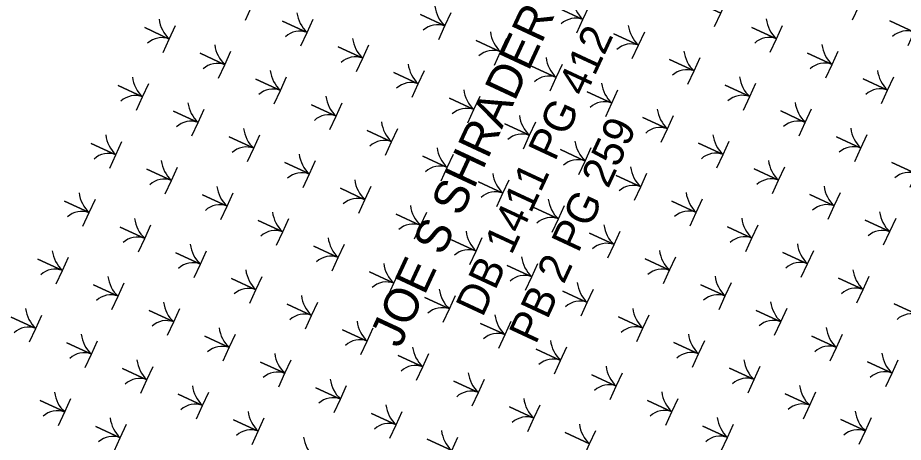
# Model space of a CAD drawing. Extents: x 2532037 to 2533565, y 713396 to 716867.
# Drawn here: x 2532692.9 to 2532822.3, y 715755.3 to 715817.2 of the extents above; entities that cross this region are included whole.
import ezdxf

# ---------------------------------------------------------------- set-up
doc = ezdxf.new("R2010")
doc.units = 0
for name, color, linetype in [('Exist Property Deed Book Text', 7, 'Continuous'), ('Exist Property Owner Text', 7, 'Continuous'), ('Scratch_Level_1', 7, 'Continuous')]:
    doc.layers.add(name, color=color, linetype=linetype)

msp = doc.modelspace()

# ---------------------------------------------------------------- linework, layer by layer
at = {"layer": 'Scratch_Level_1'}
for points in [[(2532726.17, 715816.87), (2532727.07, 715818.82), (2532723.49, 715820.47), (2532727.07, 715818.82), (2532727.97, 715820.77)], [(2532794.71, 715815.95), (2532795.62, 715817.91), (2532792.03, 715819.56), (2532795.62, 715817.91), (2532796.52, 715819.86)], [(2532814.86, 715816.9), (2532815.76, 715818.85), (2532812.17, 715820.51), (2532815.76, 715818.85), (2532816.66, 715820.8)], [(2532774.57, 715815.01), (2532775.47, 715816.96), (2532771.89, 715818.61), (2532775.47, 715816.96), (2532776.38, 715818.91)], [(2532754.43, 715814.06), (2532755.33, 715816.02), (2532751.75, 715817.67), (2532755.33, 715816.02), (2532756.23, 715817.97)], [(2532714.15, 715812.17), (2532715.05, 715814.12), (2532711.47, 715815.78), (2532715.05, 715814.12), (2532715.95, 715816.08)], [(2532734.29, 715813.12), (2532735.19, 715815.07), (2532731.61, 715816.72), (2532735.19, 715815.07), (2532736.09, 715817.02)], [(2532802.84, 715812.2), (2532803.74, 715814.16), (2532800.15, 715815.81), (2532803.74, 715814.16), (2532804.64, 715816.11)], [(2532822.98, 715813.15), (2532823.88, 715815.1), (2532820.3, 715816.76), (2532823.88, 715815.1), (2532824.78, 715817.05)], [(2532782.69, 715811.26), (2532783.6, 715813.21), (2532780.01, 715814.86), (2532783.6, 715813.21), (2532784.5, 715815.16)], [(2532742.41, 715809.37), (2532743.31, 715811.32), (2532739.73, 715812.97), (2532743.31, 715811.32), (2532744.21, 715813.27)], [(2532762.55, 715810.31), (2532763.45, 715812.27), (2532759.87, 715813.92), (2532763.45, 715812.27), (2532764.36, 715814.22)], [(2532722.27, 715808.42), (2532723.17, 715810.37), (2532719.59, 715812.03), (2532723.17, 715810.37), (2532724.07, 715812.33)], [(2532810.96, 715808.46), (2532811.86, 715810.41), (2532808.28, 715812.06), (2532811.86, 715810.41), (2532812.76, 715812.36)], [(2532790.82, 715807.51), (2532791.72, 715809.46), (2532788.13, 715811.12), (2532791.72, 715809.46), (2532792.62, 715811.41)], [(2532750.53, 715805.62), (2532751.43, 715807.57), (2532747.85, 715809.22), (2532751.43, 715807.57), (2532752.34, 715809.52)], [(2532770.67, 715806.56), (2532771.58, 715808.52), (2532767.99, 715810.17), (2532771.58, 715808.52), (2532772.48, 715810.47)], [(2532730.39, 715804.67), (2532731.29, 715806.63), (2532727.71, 715808.28), (2532731.29, 715806.63), (2532732.19, 715808.58)], [(2532819.08, 715804.71), (2532819.98, 715806.66), (2532816.4, 715808.31), (2532819.98, 715806.66), (2532820.88, 715808.61)], [(2532710.25, 715803.73), (2532711.15, 715805.68), (2532707.57, 715807.33), (2532711.15, 715805.68), (2532712.05, 715807.63)], [(2532798.94, 715803.76), (2532799.84, 715805.71), (2532796.26, 715807.37), (2532799.84, 715805.71), (2532800.74, 715807.66)], [(2532758.65, 715801.87), (2532759.56, 715803.82), (2532755.97, 715805.47), (2532759.56, 715803.82), (2532760.46, 715805.77)], [(2532778.8, 715802.81), (2532779.7, 715804.77), (2532776.11, 715806.42), (2532779.7, 715804.77), (2532780.6, 715806.72)], [(2532738.51, 715800.92), (2532739.41, 715802.88), (2532735.83, 715804.53), (2532739.41, 715802.88), (2532740.32, 715804.83)], [(2532718.37, 715799.98), (2532719.27, 715801.93), (2532715.69, 715803.58), (2532719.27, 715801.93), (2532720.17, 715803.88)], [(2532786.92, 715799.07), (2532787.82, 715801.02), (2532784.24, 715802.67), (2532787.82, 715801.02), (2532788.72, 715802.97)], [(2532807.06, 715800.01), (2532807.96, 715801.96), (2532804.38, 715803.62), (2532807.96, 715801.96), (2532808.86, 715803.92)], [(2532766.78, 715798.12), (2532767.68, 715800.07), (2532764.09, 715801.73), (2532767.68, 715800.07), (2532768.58, 715802.02)], [(2532746.63, 715797.17), (2532747.54, 715799.13), (2532743.95, 715800.78), (2532747.54, 715799.13), (2532748.44, 715801.08)], [(2532706.35, 715795.28), (2532707.25, 715797.24), (2532703.67, 715798.89), (2532707.25, 715797.24), (2532708.15, 715799.19)], [(2532726.49, 715796.23), (2532727.39, 715798.18), (2532723.81, 715799.83), (2532727.39, 715798.18), (2532728.3, 715800.13)], [(2532795.04, 715795.32), (2532795.94, 715797.27), (2532792.36, 715798.92), (2532795.94, 715797.27), (2532796.84, 715799.22)], [(2532815.18, 715796.26), (2532816.08, 715798.21), (2532812.5, 715799.87), (2532816.08, 715798.21), (2532816.98, 715800.17)], [(2532774.9, 715794.37), (2532775.8, 715796.32), (2532772.22, 715797.98), (2532775.8, 715796.32), (2532776.7, 715798.27)], [(2532754.76, 715793.42), (2532755.66, 715795.38), (2532752.08, 715797.03), (2532755.66, 715795.38), (2532756.56, 715797.33)], [(2532823.3, 715792.51), (2532824.2, 715794.46), (2532820.62, 715796.12), (2532824.2, 715794.46), (2532825.1, 715796.42)], [(2532714.47, 715791.53), (2532715.37, 715793.49), (2532711.79, 715795.14), (2532715.37, 715793.49), (2532716.28, 715795.44)], [(2532734.61, 715792.48), (2532735.52, 715794.43), (2532731.93, 715796.08), (2532735.52, 715794.43), (2532736.42, 715796.38)], [(2532803.16, 715791.57), (2532804.06, 715793.52), (2532800.48, 715795.17), (2532804.06, 715793.52), (2532804.96, 715795.47)], [(2532783.02, 715790.62), (2532783.92, 715792.57), (2532780.34, 715794.23), (2532783.92, 715792.57), (2532784.82, 715794.53)], [(2532742.74, 715788.73), (2532743.64, 715790.68), (2532740.06, 715792.34), (2532743.64, 715790.68), (2532744.54, 715792.63)], [(2532762.88, 715789.68), (2532763.78, 715791.63), (2532760.2, 715793.28), (2532763.78, 715791.63), (2532764.68, 715793.58)], [(2532722.59, 715787.78), (2532723.5, 715789.74), (2532719.91, 715791.39), (2532723.5, 715789.74), (2532724.4, 715791.69)], [(2532811.28, 715787.82), (2532812.18, 715789.77), (2532808.6, 715791.42), (2532812.18, 715789.77), (2532813.08, 715791.72)], [(2532702.45, 715786.84), (2532703.35, 715788.79), (2532699.77, 715790.44), (2532703.35, 715788.79), (2532704.26, 715790.74)], [(2532791.14, 715786.87), (2532792.04, 715788.82), (2532788.46, 715790.48), (2532792.04, 715788.82), (2532792.94, 715790.78)], [(2532750.86, 715784.98), (2532751.76, 715786.93), (2532748.18, 715788.59), (2532751.76, 715786.93), (2532752.66, 715788.88)], [(2532771, 715785.93), (2532771.9, 715787.88), (2532768.32, 715789.53), (2532771.9, 715787.88), (2532772.8, 715789.83)], [(2532730.72, 715784.03), (2532731.62, 715785.99), (2532728.04, 715787.64), (2532731.62, 715785.99), (2532732.52, 715787.94)], [(2532819.4, 715784.07), (2532820.3, 715786.02), (2532816.72, 715787.67), (2532820.3, 715786.02), (2532821.21, 715787.97)], [(2532710.57, 715783.09), (2532711.48, 715785.04), (2532707.89, 715786.69), (2532711.48, 715785.04), (2532712.38, 715786.99)], [(2532779.12, 715782.18), (2532780.02, 715784.13), (2532776.44, 715785.78), (2532780.02, 715784.13), (2532780.92, 715786.08)], [(2532799.26, 715783.12), (2532800.16, 715785.07), (2532796.58, 715786.73), (2532800.16, 715785.07), (2532801.06, 715787.03)], [(2532758.98, 715781.23), (2532759.88, 715783.18), (2532756.3, 715784.84), (2532759.88, 715783.18), (2532760.78, 715785.14)], [(2532738.84, 715780.29), (2532739.74, 715782.24), (2532736.16, 715783.89), (2532739.74, 715782.24), (2532740.64, 715784.19)], [(2532698.55, 715778.39), (2532699.46, 715780.35), (2532695.87, 715782), (2532699.46, 715780.35), (2532700.36, 715782.3)], [(2532718.7, 715779.34), (2532719.6, 715781.29), (2532716.02, 715782.95), (2532719.6, 715781.29), (2532720.5, 715783.24)], [(2532787.24, 715778.43), (2532788.14, 715780.38), (2532784.56, 715782.03), (2532788.14, 715780.38), (2532789.04, 715782.33)], [(2532807.38, 715779.37), (2532808.28, 715781.33), (2532804.7, 715782.98), (2532808.28, 715781.33), (2532809.19, 715783.28)], [(2532767.1, 715777.48), (2532768, 715779.43), (2532764.42, 715781.09), (2532768, 715779.43), (2532768.9, 715781.39)], [(2532746.96, 715776.54), (2532747.86, 715778.49), (2532744.28, 715780.14), (2532747.86, 715778.49), (2532748.76, 715780.44)], [(2532706.68, 715774.64), (2532707.58, 715776.6), (2532704, 715778.25), (2532707.58, 715776.6), (2532708.48, 715778.55)], [(2532726.82, 715775.59), (2532727.72, 715777.54), (2532724.14, 715779.2), (2532727.72, 715777.54), (2532728.62, 715779.49)], [(2532795.36, 715774.68), (2532796.26, 715776.63), (2532792.68, 715778.28), (2532796.26, 715776.63), (2532797.17, 715778.58)], [(2532815.5, 715775.62), (2532816.41, 715777.58), (2532812.82, 715779.23), (2532816.41, 715777.58), (2532817.31, 715779.53)], [(2532775.22, 715773.73), (2532776.12, 715775.68), (2532772.54, 715777.34), (2532776.12, 715775.68), (2532777.02, 715777.64)], [(2532734.94, 715771.84), (2532735.84, 715773.79), (2532732.26, 715775.45), (2532735.84, 715773.79), (2532736.74, 715775.75)], [(2532755.08, 715772.79), (2532755.98, 715774.74), (2532752.4, 715776.39), (2532755.98, 715774.74), (2532756.88, 715776.69)], [(2532823.63, 715771.87), (2532824.53, 715773.83), (2532820.95, 715775.48), (2532824.53, 715773.83), (2532825.43, 715775.78)], [(2532714.8, 715770.9), (2532715.7, 715772.85), (2532712.12, 715774.5), (2532715.7, 715772.85), (2532716.6, 715774.8)], [(2532803.48, 715770.93), (2532804.39, 715772.88), (2532800.8, 715774.53), (2532804.39, 715772.88), (2532805.29, 715774.83)], [(2532694.66, 715769.95), (2532695.56, 715771.9), (2532691.98, 715773.56), (2532695.56, 715771.9), (2532696.46, 715773.85)], [(2532783.34, 715769.98), (2532784.24, 715771.94), (2532780.66, 715773.59), (2532784.24, 715771.94), (2532785.15, 715773.89)], [(2532743.06, 715768.09), (2532743.96, 715770.04), (2532740.38, 715771.7), (2532743.96, 715770.04), (2532744.86, 715772)], [(2532763.2, 715769.04), (2532764.1, 715770.99), (2532760.52, 715772.64), (2532764.1, 715770.99), (2532765, 715772.94)], [(2532722.92, 715767.15), (2532723.82, 715769.1), (2532720.24, 715770.75), (2532723.82, 715769.1), (2532724.72, 715771.05)], [(2532811.61, 715767.18), (2532812.51, 715769.13), (2532808.93, 715770.78), (2532812.51, 715769.13), (2532813.41, 715771.08)], [(2532702.78, 715766.2), (2532703.68, 715768.15), (2532700.1, 715769.81), (2532703.68, 715768.15), (2532704.58, 715770.1)], [(2532791.46, 715766.23), (2532792.37, 715768.19), (2532788.78, 715769.84), (2532792.37, 715768.19), (2532793.27, 715770.14)], [(2532751.18, 715764.34), (2532752.08, 715766.29), (2532748.5, 715767.95), (2532752.08, 715766.29), (2532752.98, 715768.25)], [(2532771.32, 715765.29), (2532772.22, 715767.24), (2532768.64, 715768.89), (2532772.22, 715767.24), (2532773.13, 715769.19)], [(2532731.04, 715763.4), (2532731.94, 715765.35), (2532728.36, 715767), (2532731.94, 715765.35), (2532732.84, 715767.3)], [(2532819.73, 715763.43), (2532820.63, 715765.38), (2532817.05, 715767.04), (2532820.63, 715765.38), (2532821.53, 715767.33)], [(2532710.9, 715762.45), (2532711.8, 715764.4), (2532708.22, 715766.06), (2532711.8, 715764.4), (2532712.7, 715766.36)], [(2532779.44, 715761.54), (2532780.35, 715763.49), (2532776.76, 715765.14), (2532780.35, 715763.49), (2532781.25, 715765.44)], [(2532799.59, 715762.48), (2532800.49, 715764.44), (2532796.91, 715766.09), (2532800.49, 715764.44), (2532801.39, 715766.39)], [(2532759.3, 715760.59), (2532760.2, 715762.55), (2532756.62, 715764.2), (2532760.2, 715762.55), (2532761.11, 715764.5)], [(2532739.16, 715759.65), (2532740.06, 715761.6), (2532736.48, 715763.25), (2532740.06, 715761.6), (2532740.96, 715763.55)], [(2532698.88, 715757.76), (2532699.78, 715759.71), (2532696.2, 715761.36), (2532699.78, 715759.71), (2532700.68, 715761.66)], [(2532719.02, 715758.7), (2532719.92, 715760.65), (2532716.34, 715762.31), (2532719.92, 715760.65), (2532720.82, 715762.61)], [(2532787.57, 715757.79), (2532788.47, 715759.74), (2532784.89, 715761.39), (2532788.47, 715759.74), (2532789.37, 715761.69)], [(2532807.71, 715758.73), (2532808.61, 715760.69), (2532805.03, 715762.34), (2532808.61, 715760.69), (2532809.51, 715762.64)], [(2532767.42, 715756.84), (2532768.33, 715758.8), (2532764.74, 715760.45), (2532768.33, 715758.8), (2532769.23, 715760.75)], [(2532747.28, 715755.9), (2532748.18, 715757.85), (2532744.6, 715759.5), (2532748.18, 715757.85), (2532749.09, 715759.8)], [(2532815.83, 715754.99), (2532816.73, 715756.94), (2532813.15, 715758.59), (2532816.73, 715756.94), (2532817.63, 715758.89)], [(2532707, 715754.01), (2532707.9, 715755.96), (2532704.32, 715757.61), (2532707.9, 715755.96), (2532708.8, 715757.91)], [(2532727.14, 715754.95), (2532728.04, 715756.9), (2532724.46, 715758.56), (2532728.04, 715756.9), (2532728.94, 715758.86)], [(2532795.69, 715754.04), (2532796.59, 715755.99), (2532793.01, 715757.65), (2532796.59, 715755.99), (2532797.49, 715757.94)], [(2532775.55, 715753.09), (2532776.45, 715755.05), (2532772.87, 715756.7), (2532776.45, 715755.05), (2532777.35, 715757)], [(2532755.4, 715752.15), (2532756.31, 715754.1), (2532752.72, 715755.75), (2532756.31, 715754.1), (2532757.21, 715756.05)]]:
    msp.add_lwpolyline(points, dxfattribs=at)
for centre, radius, start, end in [((2532778.76, 715820.47), 4.81, 187.3464, 226.8412), ((2532758.62, 715819.52), 4.81, 187.3464, 226.8412), ((2532738.48, 715818.57), 4.81, 187.3464, 226.8412), ((2532774.39, 715814.08), 3.07, 69.3593, 132.7539), ((2532718.34, 715817.63), 4.81, 187.3464, 226.8412), ((2532754.25, 715813.14), 3.07, 69.3593, 132.7539), ((2532786.88, 715816.72), 4.81, 187.3464, 226.8412), ((2532807.02, 715817.66), 4.81, 187.3464, 226.8412), ((2532734.11, 715812.19), 3.07, 69.3593, 132.7539), ((2532766.74, 715815.77), 4.81, 187.3464, 226.8412), ((2532822.79, 715812.23), 3.07, 69.3593, 132.7539), ((2532713.97, 715811.25), 3.07, 69.3593, 132.7539), ((2532726.46, 715813.88), 4.81, 187.3464, 226.8412), ((2532746.6, 715814.83), 4.81, 187.3464, 226.8412), ((2532782.51, 715810.33), 3.07, 69.3593, 132.7539), ((2532802.65, 715811.28), 3.07, 69.3593, 132.7539), ((2532815.15, 715813.91), 4.81, 187.3464, 226.8412), ((2532762.37, 715809.39), 3.07, 69.3593, 132.7539), ((2532795, 715812.97), 4.81, 187.3464, 226.8412), ((2532742.23, 715808.44), 3.07, 69.3593, 132.7539), ((2532774.86, 715812.02), 4.81, 187.3464, 226.8412), ((2532722.09, 715807.5), 3.07, 69.3593, 132.7539), ((2532734.58, 715810.13), 4.81, 187.3464, 226.8412), ((2532754.72, 715811.08), 4.81, 187.3464, 226.8412), ((2532790.63, 715806.58), 3.07, 69.3593, 132.7539), ((2532810.77, 715807.53), 3.07, 69.3593, 132.7539), ((2532823.27, 715810.16), 4.81, 187.3464, 226.8412), ((2532714.44, 715809.18), 4.81, 187.3464, 226.8412), ((2532770.49, 715805.64), 3.07, 69.3593, 132.7539), ((2532803.13, 715809.22), 4.81, 187.3464, 226.8412), ((2532730.21, 715803.75), 3.07, 69.3593, 132.7539), ((2532750.35, 715804.69), 3.07, 69.3593, 132.7539), ((2532782.98, 715808.27), 4.81, 187.3464, 226.8412), ((2532818.9, 715803.78), 3.07, 69.3593, 132.7539), ((2532710.07, 715802.8), 3.07, 69.3593, 132.7539), ((2532742.7, 715806.38), 4.81, 187.3464, 226.8412), ((2532762.84, 715807.33), 4.81, 187.3464, 226.8412), ((2532798.75, 715802.84), 3.07, 69.3593, 132.7539), ((2532722.56, 715805.44), 4.81, 187.3464, 226.8412), ((2532778.61, 715801.89), 3.07, 69.3593, 132.7539), ((2532811.25, 715805.47), 4.81, 187.3464, 226.8412), ((2532738.33, 715800), 3.07, 69.3593, 132.7539), ((2532758.47, 715800.94), 3.07, 69.3593, 132.7539), ((2532770.96, 715803.58), 4.81, 187.3464, 226.8412), ((2532791.11, 715804.52), 4.81, 187.3464, 226.8412), ((2532718.19, 715799.05), 3.07, 69.3593, 132.7539), ((2532750.82, 715802.63), 4.81, 187.3464, 226.8412), ((2532806.88, 715799.09), 3.07, 69.3593, 132.7539), ((2532730.68, 715801.69), 4.81, 187.3464, 226.8412), ((2532766.59, 715797.19), 3.07, 69.3593, 132.7539), ((2532786.73, 715798.14), 3.07, 69.3593, 132.7539), ((2532819.37, 715801.72), 4.81, 187.3464, 226.8412), ((2532710.54, 715800.74), 4.81, 187.3464, 226.8412), ((2532746.45, 715796.25), 3.07, 69.3593, 132.7539), ((2532779.09, 715799.83), 4.81, 187.3464, 226.8412), ((2532799.23, 715800.77), 4.81, 187.3464, 226.8412), ((2532726.31, 715795.3), 3.07, 69.3593, 132.7539), ((2532758.94, 715798.88), 4.81, 187.3464, 226.8412), ((2532815, 715795.34), 3.07, 69.3593, 132.7539), ((2532706.17, 715794.36), 3.07, 69.3593, 132.7539), ((2532738.8, 715797.94), 4.81, 187.3464, 226.8412), ((2532774.71, 715793.45), 3.07, 69.3593, 132.7539), ((2532794.86, 715794.39), 3.07, 69.3593, 132.7539), ((2532807.35, 715797.02), 4.81, 187.3464, 226.8412), ((2532718.66, 715796.99), 4.81, 187.3464, 226.8412), ((2532754.57, 715792.5), 3.07, 69.3593, 132.7539), ((2532787.21, 715796.08), 4.81, 187.3464, 226.8412), ((2532734.43, 715791.55), 3.07, 69.3593, 132.7539), ((2532767.07, 715795.13), 4.81, 187.3464, 226.8412), ((2532823.12, 715791.59), 3.07, 69.3593, 132.7539), ((2532714.29, 715790.61), 3.07, 69.3593, 132.7539), ((2532726.78, 715793.24), 4.81, 187.3464, 226.8412), ((2532746.92, 715794.19), 4.81, 187.3464, 226.8412), ((2532782.84, 715789.7), 3.07, 69.3593, 132.7539), ((2532802.98, 715790.64), 3.07, 69.3593, 132.7539), ((2532815.47, 715793.27), 4.81, 187.3464, 226.8412), ((2532706.64, 715792.3), 4.81, 187.3464, 226.8412), ((2532762.69, 715788.75), 3.07, 69.3593, 132.7539), ((2532795.33, 715792.33), 4.81, 187.3464, 226.8412), ((2532722.41, 715786.86), 3.07, 69.3593, 132.7539), ((2532742.55, 715787.8), 3.07, 69.3593, 132.7539), ((2532775.19, 715791.38), 4.81, 187.3464, 226.8412), ((2532811.1, 715786.89), 3.07, 69.3593, 132.7539), ((2532702.27, 715785.91), 3.07, 69.3593, 132.7539), ((2532734.9, 715789.49), 4.81, 187.3464, 226.8412), ((2532755.05, 715790.44), 4.81, 187.3464, 226.8412), ((2532790.96, 715785.95), 3.07, 69.3593, 132.7539), ((2532823.59, 715789.53), 4.81, 187.3464, 226.8412), ((2532714.76, 715788.55), 4.81, 187.3464, 226.8412), ((2532770.82, 715785), 3.07, 69.3593, 132.7539), ((2532803.45, 715788.58), 4.81, 187.3464, 226.8412), ((2532730.53, 715783.11), 3.07, 69.3593, 132.7539), ((2532750.67, 715784.06), 3.07, 69.3593, 132.7539), ((2532763.17, 715786.69), 4.81, 187.3464, 226.8412), ((2532783.31, 715787.63), 4.81, 187.3464, 226.8412), ((2532819.22, 715783.14), 3.07, 69.3593, 132.7539), ((2532710.39, 715782.16), 3.07, 69.3593, 132.7539), ((2532743.03, 715785.74), 4.81, 187.3464, 226.8412), ((2532799.08, 715782.2), 3.07, 69.3593, 132.7539), ((2532722.88, 715784.8), 4.81, 187.3464, 226.8412), ((2532778.94, 715781.25), 3.07, 69.3593, 132.7539), ((2532811.57, 715784.83), 4.81, 187.3464, 226.8412), ((2532702.74, 715783.85), 4.81, 187.3464, 226.8412), ((2532738.65, 715779.36), 3.07, 69.3593, 132.7539), ((2532758.8, 715780.31), 3.07, 69.3593, 132.7539), ((2532771.29, 715782.94), 4.81, 187.3464, 226.8412), ((2532791.43, 715783.88), 4.81, 187.3464, 226.8412), ((2532718.51, 715778.41), 3.07, 69.3593, 132.7539), ((2532751.15, 715781.99), 4.81, 187.3464, 226.8412), ((2532807.2, 715778.45), 3.07, 69.3593, 132.7539), ((2532698.37, 715777.47), 3.07, 69.3593, 132.7539), ((2532731.01, 715781.05), 4.81, 187.3464, 226.8412), ((2532766.92, 715776.56), 3.07, 69.3593, 132.7539), ((2532787.06, 715777.5), 3.07, 69.3593, 132.7539), ((2532819.69, 715781.08), 4.81, 187.3464, 226.8412), ((2532710.86, 715780.1), 4.81, 187.3464, 226.8412), ((2532746.78, 715775.61), 3.07, 69.3593, 132.7539), ((2532779.41, 715779.19), 4.81, 187.3464, 226.8412), ((2532799.55, 715780.14), 4.81, 187.3464, 226.8412), ((2532726.63, 715774.67), 3.07, 69.3593, 132.7539), ((2532759.27, 715778.24), 4.81, 187.3464, 226.8412), ((2532815.32, 715774.7), 3.07, 69.3593, 132.7539), ((2532706.49, 715773.72), 3.07, 69.3593, 132.7539), ((2532718.99, 715776.35), 4.81, 187.3464, 226.8412), ((2532739.13, 715777.3), 4.81, 187.3464, 226.8412), ((2532775.04, 715772.81), 3.07, 69.3593, 132.7539), ((2532795.18, 715773.75), 3.07, 69.3593, 132.7539), ((2532807.67, 715776.39), 4.81, 187.3464, 226.8412), ((2532698.84, 715775.41), 4.81, 187.3464, 226.8412), ((2532754.9, 715771.86), 3.07, 69.3593, 132.7539), ((2532787.53, 715775.44), 4.81, 187.3464, 226.8412), ((2532734.76, 715770.92), 3.07, 69.3593, 132.7539), ((2532767.39, 715774.49), 4.81, 187.3464, 226.8412), ((2532823.44, 715770.95), 3.07, 69.3593, 132.7539), ((2532694.47, 715769.02), 3.07, 69.3593, 132.7539), ((2532714.62, 715769.97), 3.07, 69.3593, 132.7539), ((2532727.11, 715772.6), 4.81, 187.3464, 226.8412), ((2532747.25, 715773.55), 4.81, 187.3464, 226.8412), ((2532783.16, 715769.06), 3.07, 69.3593, 132.7539), ((2532803.3, 715770), 3.07, 69.3593, 132.7539), ((2532815.79, 715772.64), 4.81, 187.3464, 226.8412), ((2532706.97, 715771.66), 4.81, 187.3464, 226.8412), ((2532763.02, 715768.11), 3.07, 69.3593, 132.7539), ((2532795.65, 715771.69), 4.81, 187.3464, 226.8412), ((2532722.74, 715766.22), 3.07, 69.3593, 132.7539), ((2532742.88, 715767.17), 3.07, 69.3593, 132.7539), ((2532775.51, 715770.75), 4.81, 187.3464, 226.8412), ((2532811.42, 715766.25), 3.07, 69.3593, 132.7539), ((2532702.6, 715765.28), 3.07, 69.3593, 132.7539), ((2532735.23, 715768.85), 4.81, 187.3464, 226.8412), ((2532755.37, 715769.8), 4.81, 187.3464, 226.8412), ((2532791.28, 715765.31), 3.07, 69.3593, 132.7539), ((2532823.92, 715768.89), 4.81, 187.3464, 226.8412), ((2532715.09, 715767.91), 4.81, 187.3464, 226.8412), ((2532771.14, 715764.36), 3.07, 69.3593, 132.7539), ((2532803.77, 715767.94), 4.81, 187.3464, 226.8412), ((2532730.86, 715762.47), 3.07, 69.3593, 132.7539), ((2532751, 715763.42), 3.07, 69.3593, 132.7539), ((2532763.49, 715766.05), 4.81, 187.3464, 226.8412), ((2532783.63, 715767), 4.81, 187.3464, 226.8412), ((2532819.54, 715762.5), 3.07, 69.3593, 132.7539), ((2532710.72, 715761.53), 3.07, 69.3593, 132.7539), ((2532743.35, 715765.11), 4.81, 187.3464, 226.8412), ((2532799.4, 715761.56), 3.07, 69.3593, 132.7539), ((2532723.21, 715764.16), 4.81, 187.3464, 226.8412), ((2532779.26, 715760.61), 3.07, 69.3593, 132.7539), ((2532811.9, 715764.19), 4.81, 187.3464, 226.8412), ((2532703.07, 715763.21), 4.81, 187.3464, 226.8412), ((2532738.98, 715758.72), 3.07, 69.3593, 132.7539), ((2532759.12, 715759.67), 3.07, 69.3593, 132.7539), ((2532771.61, 715762.3), 4.81, 187.3464, 226.8412), ((2532791.75, 715763.25), 4.81, 187.3464, 226.8412), ((2532718.84, 715757.78), 3.07, 69.3593, 132.7539), ((2532751.47, 715761.36), 4.81, 187.3464, 226.8412), ((2532807.52, 715757.81), 3.07, 69.3593, 132.7539), ((2532698.7, 715756.83), 3.07, 69.3593, 132.7539), ((2532731.33, 715760.41), 4.81, 187.3464, 226.8412), ((2532767.24, 715755.92), 3.07, 69.3593, 132.7539), ((2532787.38, 715756.86), 3.07, 69.3593, 132.7539), ((2532799.88, 715759.5), 4.81, 187.3464, 226.8412), ((2532820.02, 715760.44), 4.81, 187.3464, 226.8412), ((2532711.19, 715759.46), 4.81, 187.3464, 226.8412), ((2532747.1, 715754.97), 3.07, 69.3593, 132.7539), ((2532779.73, 715758.55), 4.81, 187.3464, 226.8412), ((2532726.96, 715754.03), 3.07, 69.3593, 132.7539), ((2532759.59, 715757.61), 4.81, 187.3464, 226.8412), ((2532815.65, 715754.06), 3.07, 69.3593, 132.7539), ((2532706.82, 715753.08), 3.07, 69.3593, 132.7539), ((2532739.45, 715756.66), 4.81, 187.3464, 226.8412), ((2532795.5, 715753.11), 3.07, 69.3593, 132.7539)]:
    msp.add_arc(centre, radius, start, end, dxfattribs=at)

# ---------------------------------------------------------------- texts
at = {"layer": 'Exist Property Deed Book Text'}
for s, p in [('DB 1411 PG 412', (2532760.81, 715773.4)), ('PB 2 PG 259', (2532768.58, 715769.44))]:
    msp.add_text(s, height=4.5, rotation=65.05, dxfattribs=at).set_placement(p)
at = {"layer": 'Exist Property Owner Text'}
msp.add_text('JOE S SHRADER', height=5, rotation=65.05, dxfattribs=at).set_placement((2532748.73, 715768.87))

doc.saveas('drawing.dxf')
